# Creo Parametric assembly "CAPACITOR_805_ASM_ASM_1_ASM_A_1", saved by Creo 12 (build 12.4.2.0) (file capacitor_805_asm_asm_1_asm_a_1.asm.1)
Units: Custom; MM, KILOGRAM, SECS

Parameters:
  PTC_WM_ITERATION = "0"
  PTC_WM_VERSION = "-.0"
  PTC_WM_LIFECYCLE_STATE = "In Work"
  PTC_WM_LIFECYCLE = "MO_CADDocument"
  PTC_WM_CREATED_BY = "Maximilian Roepper (Z0017RMS: MO)"
  PTC_WM_CREATED_ON = "18-Sep-26 11:36:42 AM"
  PTC_WM_MODIFIED_BY = "Maximilian Roepper (Z0017RMS: MO)"
  PTC_WM_MODIFIED_ON = "18-Sep-26 11:36:46 AM"
  PDMLINKNUMBER = "PDM000071454779"
  PTC_WM_NUMBER = "PDM000071454779"

Other parameters: WEIGHT, WEIGHT_FACTOR, WEIGHT_ADD, MC_ERRORS, SUPPLIER

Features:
  1. coordinate system
  2. imported feature
  3. component "VALOR_PREDETERMINADO_5_PRT_1__1"

Other named items: DRW_VIEW_ORG, ROUGH-GROB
